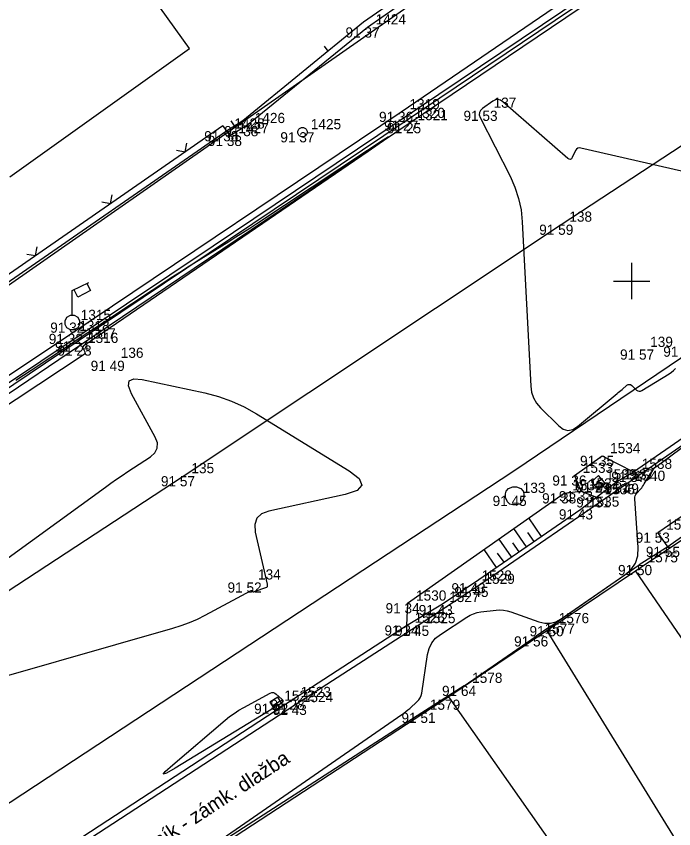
# Model space of a CAD drawing. Extents: x -711081 to -709338, y -1025122 to -1024092.
# Drawn here: x -710916.9 to -710898.84, y -1025015.05 to -1024992.72 of the extents above; entities that cross this region are included whole.
import ezdxf

# ---------------------------------------------------------------- set-up
doc = ezdxf.new("R2010")
doc.units = 0
for name, color, linetype in [('Ex_Minor Contours', 7, 'Continuous'), ('Z_body', 7, 'Continuous'), ('Z_body_cisla', 7, 'Continuous'), ('Z_body_vysky_redukovane', 7, 'Continuous'), ('Z_budova', 7, 'Continuous'), ('Z_hektometricka_sit', 7, 'Continuous'), ('Z_hrany_paty', 7, 'Continuous'), ('Z_katastr_hranice', 7, 'Continuous'), ('Z_katastr_vnitrni_kresba', 7, 'Continuous'), ('Z_komunikace', 7, 'Continuous'), ('Z_komunikace_osa', 7, 'Continuous'), ('Z_obruba', 7, 'Continuous'), ('Z_pilire', 7, 'Continuous'), ('Z_ploty', 7, 'Continuous'), ('Z_ploty_znacky', 7, 'Continuous'), ('Z_popisy', 7, 'Continuous'), ('Z_rozhranni', 7, 'Continuous'), ('Z_site_kanalizace_znaky', 7, 'Continuous'), ('Z_site_vo_znaky', 7, 'Continuous'), ('Z_site_vodovod_znaky', 7, 'Continuous'), ('Z_technicke_srafy', 7, 'Continuous'), ('Z_vstupy', 7, 'Continuous')]:
    doc.layers.add(name, color=color, linetype=linetype)

# ---------------------------------------------------------------- blocks, each defined once
blk = doc.blocks.new('POINT_DISPLAY')
blk.add_line((0, 0), (0, 0))
blk = doc.blocks.new('Z210')
blk.add_line((0, 0), (0, 0.17))
blk = doc.blocks.new('Z212')
for p, q in [((-0.17, 0.17), (0, 0)), ((0, 0), (0.17, 0.17))]:
    blk.add_line(p, q)
blk = doc.blocks.new('Z614')
for p, q in [((-0.13, 0.03), (-0.1, 0.08)), ((-0.13, -0.03), (-0.13, 0.03)), ((-0.1, 0.08), (-0.08, 0.1)), ((-0.08, 0.1), (-0.03, 0.13)), ((-0.03, 0.13), (0.03, 0.13)), ((0.03, 0.13), (0.08, 0.1)), ((0.08, 0.1), (0.1, 0.08)), ((0.1, 0.08), (0.13, 0.03)), ((0.13, 0.03), (0.13, -0.03)), ((-0.1, -0.08), (-0.13, -0.03)), ((-0.08, -0.1), (-0.1, -0.08)), ((-0.03, -0.13), (-0.08, -0.1)), ((0.03, -0.13), (-0.03, -0.13)), ((0.08, -0.1), (0.03, -0.13)), ((0.1, -0.08), (0.08, -0.1)), ((0.13, -0.03), (0.1, -0.08))]:
    blk.add_line(p, q)
blk = doc.blocks.new('Z13')
for p, q in [((0, 0.88), (0.45, 1.1)), ((0.15, 0.7), (0.05, 0.9)), ((0.4, 1.07), (0.5, 0.88)), ((0, 0.2), (0, 0.88)), ((0.5, 0.88), (0.15, 0.7)), ((-0.2, 0.05), (-0.15, 0.15)), ((-0.2, -0.05), (-0.2, 0.05)), ((-0.15, 0.15), (-0.05, 0.2)), ((-0.05, 0.2), (0.05, 0.2)), ((0.05, 0.2), (0.15, 0.15)), ((0.15, 0.15), (0.2, 0.05)), ((0.2, 0.05), (0.2, -0.05)), ((-0.15, -0.15), (-0.2, -0.05)), ((-0.05, -0.2), (-0.15, -0.15)), ((0.05, -0.2), (-0.05, -0.2)), ((0.15, -0.15), (0.05, -0.2)), ((0.2, -0.05), (0.15, -0.15))]:
    blk.add_line(p, q)
blk = doc.blocks.new('Z620')
for p, q in [((-0.17, 0.2), (-0.05, 0.25)), ((-0.05, 0.25), (0.05, 0.25)), ((0.05, 0.25), (0.17, 0.2)), ((-0.25, 0.05), (-0.23, 0.13)), ((-0.25, -0.05), (-0.25, 0.05)), ((-0.23, 0.13), (-0.17, 0.2)), ((0.17, 0.2), (0.23, 0.13)), ((0.23, 0.13), (0.25, 0.05)), ((0.25, 0.05), (0.25, -0.05)), ((-0.2, -0.17), (-0.25, -0.05)), ((-0.13, -0.23), (-0.2, -0.17)), ((0.2, -0.17), (0.13, -0.23)), ((0.25, -0.05), (0.2, -0.17)), ((-0.05, -0.25), (-0.13, -0.23)), ((0.05, -0.25), (-0.05, -0.25)), ((0.13, -0.23), (0.05, -0.25))]:
    blk.add_line(p, q)
blk = doc.blocks.new('Z46260')
for p, q in [((0.13, 0.13), (-0.13, 0.13)), ((-0.13, 0.13), (-0.13, -0.13)), ((0.13, 0), (-0.13, 0)), ((0.13, -0.13), (0.13, 0.13)), ((-0.13, -0.13), (0.13, -0.13))]:
    blk.add_line(p, q)

msp = doc.modelspace()

# ---------------------------------------------------------------- linework, layer by layer
at = {"layer": 'Ex_Minor Contours'}
for points in [[(-710896.068, -1024997.571), (-710901.392, -1024996.347), (-710901.439, -1024996.342), (-710901.479, -1024996.353), (-710901.512, -1024996.377), (-710901.539, -1024996.417), (-710901.629, -1024996.604), (-710901.654, -1024996.641), (-710901.682, -1024996.657), (-710901.715, -1024996.654), (-710901.752, -1024996.63), (-710903.534, -1024995.076), (-710903.6, -1024995.033), (-710903.668, -1024995.015), (-710903.737, -1024995.025), (-710903.807, -1024995.061), (-710904.093, -1024995.258), (-710904.15, -1024995.311), (-710904.18, -1024995.37), (-710904.182, -1024995.437), (-710904.156, -1024995.511), (-710903.336, -1024997.123), (-710903.203, -1024997.422), (-710903.103, -1024997.729), (-710903.036, -1024998.046), (-710903.003, -1024998.371), (-710902.771, -1025002.888), (-710902.747, -1025003.057), (-710902.695, -1025003.213), (-710902.613, -1025003.356), (-710902.503, -1025003.486), (-710902.002, -1025003.979), (-710901.876, -1025004.072), (-710901.747, -1025004.107), (-710901.616, -1025004.083), (-710901.482, -1025003.999), (-710900.397, -1025003.09), (-710900.364, -1025003.062), (-710900.33, -1025003.033), (-710900.296, -1025003.005), (-710900.263, -1025002.977), (-710900.128, -1025002.865), (-710900.094, -1025002.844), (-710900.061, -1025002.838), (-710900.028, -1025002.846), (-710899.996, -1025002.869), (-710899.861, -1025002.994), (-710899.827, -1025003.018), (-710899.791, -1025003.029), (-710899.755, -1025003.026), (-710899.717, -1025003.009), (-710898.969, -1025002.552), (-710898.904, -1025002.507), (-710898.845, -1025002.456), (-710898.792, -1025002.399)], [(-710920.621, -1025005.7), (-710915.035, -1025002.009), (-710915.018, -1025001.994), (-710915.01, -1025001.977), (-710915.009, -1025001.958), (-710915.017, -1025001.936), (-710915.066, -1025001.847), (-710915.074, -1025001.826), (-710915.073, -1025001.806), (-710915.065, -1025001.789), (-710915.048, -1025001.774), (-710907.239, -1024996.433), (-710906.817, -1024996.142), (-710906.678, -1024996.042), (-710906.823, -1024996.133), (-710907.251, -1024996.415), (-710910.297, -1024998.43), (-710910.486, -1024998.554), (-710910.677, -1024998.677), (-710910.868, -1024998.799), (-710911.06, -1024998.919), (-710911.831, -1024999.398), (-710912.024, -1024999.518), (-710912.215, -1024999.639), (-710912.406, -1024999.762), (-710912.595, -1024999.886), (-710914.298, -1025001.009), (-710914.393, -1025001.071), (-710914.488, -1025001.134), (-710914.584, -1025001.197), (-710914.679, -1025001.259), (-710915.061, -1025001.509), (-710915.156, -1025001.571), (-710915.251, -1025001.634), (-710915.346, -1025001.697), (-710915.441, -1025001.76), (-710916.495, -1025002.457), (-710916.703, -1025002.594), (-710916.91, -1025002.731)], [(-710919.801, -1025009.546), (-710914.45, -1025005.662), (-710914.299, -1025005.553), (-710914.146, -1025005.446), (-710913.992, -1025005.341), (-710913.838, -1025005.237), (-710913.216, -1025004.826), (-710913.091, -1025004.716), (-710913.027, -1025004.59), (-710913.024, -1025004.449), (-710913.082, -1025004.293), (-710913.733, -1025003.095), (-710913.818, -1025002.88), (-710913.798, -1025002.744), (-710913.673, -1025002.686), (-710913.443, -1025002.707), (-710911.723, -1025003.075), (-710911.349, -1025003.172), (-710910.986, -1025003.3), (-710910.636, -1025003.458), (-710910.298, -1025003.647), (-710907.754, -1025005.214), (-710907.481, -1025005.427), (-710907.408, -1025005.606), (-710907.536, -1025005.751), (-710907.865, -1025005.862), (-710909.961, -1025006.318), (-710910.165, -1025006.393), (-710910.295, -1025006.516), (-710910.351, -1025006.686), (-710910.334, -1025006.902), (-710910.012, -1025008.327), (-710910.01, -1025008.335), (-710910.009, -1025008.343), (-710910.008, -1025008.352), (-710910.009, -1025008.36), (-710910.01, -1025008.394), (-710910.012, -1025008.402), (-710910.015, -1025008.408), (-710910.02, -1025008.413), (-710910.027, -1025008.417), (-710910.376, -1025008.543), (-710910.383, -1025008.544), (-710910.391, -1025008.544), (-710910.398, -1025008.541), (-710910.404, -1025008.537), (-710910.429, -1025008.514), (-710910.435, -1025008.509), (-710910.442, -1025008.507), (-710910.449, -1025008.507), (-710910.456, -1025008.51), (-710911.718, -1025009.187), (-710911.933, -1025009.295), (-710912.153, -1025009.392), (-710912.378, -1025009.476), (-710912.608, -1025009.548), (-710918.944, -1025011.362)], [(-710912.431, -1025016.148), (-710906.311, -1025011.912), (-710906.254, -1025011.871), (-710906.199, -1025011.829), (-710906.145, -1025011.785), (-710906.093, -1025011.74), (-710905.885, -1025011.554), (-710905.839, -1025011.505), (-710905.802, -1025011.45), (-710905.777, -1025011.39), (-710905.761, -1025011.324), (-710905.603, -1025010.259), (-710905.561, -1025010.092), (-710905.489, -1025009.944), (-710905.385, -1025009.816), (-710905.25, -1025009.707), (-710904.525, -1025009.231), (-710904.435, -1025009.179), (-710904.341, -1025009.139), (-710904.243, -1025009.109), (-710904.141, -1025009.091), (-710903.723, -1025009.043), (-710903.62, -1025009.036), (-710903.517, -1025009.042), (-710903.416, -1025009.059), (-710903.317, -1025009.089), (-710902.544, -1025009.365), (-710902.384, -1025009.403), (-710902.23, -1025009.402), (-710902.081, -1025009.363), (-710901.937, -1025009.285), (-710900.182, -1025008.071), (-710900.013, -1025007.923), (-710899.896, -1025007.749), (-710899.832, -1025007.549), (-710899.822, -1025007.324), (-710899.912, -1025005.982), (-710899.911, -1025005.941), (-710899.902, -1025005.903), (-710899.885, -1025005.867), (-710899.861, -1025005.835), (-710899.748, -1025005.709), (-710899.721, -1025005.677), (-710899.696, -1025005.643), (-710899.672, -1025005.609), (-710899.65, -1025005.573), (-710899.484, -1025005.285), (-710899.447, -1025005.227), (-710899.404, -1025005.174), (-710899.357, -1025005.126), (-710899.303, -1025005.083), (-710897.795, -1025003.971)]]:
    msp.add_lwpolyline(points, dxfattribs=at)
msp.add_lwpolyline([(-710912.772, -1025013.521), (-710912.863, -1025013.551), (-710912.806, -1025013.474), (-710912.601, -1025013.29), (-710911.163, -1025012.066), (-710911.043, -1025011.968), (-710910.918, -1025011.878), (-710910.788, -1025011.794), (-710910.654, -1025011.717), (-710909.923, -1025011.325), (-710909.879, -1025011.308), (-710909.837, -1025011.306), (-710909.797, -1025011.319), (-710909.758, -1025011.347), (-710909.61, -1025011.486), (-710909.582, -1025011.519), (-710909.575, -1025011.551), (-710909.589, -1025011.581), (-710909.622, -1025011.608), (-710912.533, -1025013.384)], close=True, dxfattribs=at)
at = {"layer": 'Z_budova'}
for p, q in [((-710897.68, -1025006.36), (-710899, -1025007.3)), ((-710899, -1025007.3), (-710899.79, -1025007.8)), ((-710902.22, -1025009.48), (-710902.62, -1025009.76)), ((-710904.6, -1025011.12), (-710905.76, -1025011.86)), ((-710905.76, -1025011.86), (-710912.65, -1025016.3))]:
    msp.add_line(p, q, dxfattribs=at)
at = {"layer": 'Z_hektometricka_sit'}
for p, q in [((-710900, -1024999.5), (-710900, -1025000.5)), ((-710900.5, -1025000), (-710899.5, -1025000))]:
    msp.add_line(p, q, dxfattribs=at)
at = {"layer": 'Z_hrany_paty'}
for p, q in [((-710901.57, -1025005.34), (-710900.81, -1025004.8)), ((-710900.81, -1025004.8), (-710899.95, -1025005.24)), ((-710901.57, -1025005.34), (-710901.39, -1025005.77)), ((-710906.15, -1025008.85), (-710901.85, -1025005.83)), ((-710901.85, -1025005.83), (-710901.39, -1025005.77)), ((-710901.39, -1025005.77), (-710900.96, -1025005.94)), ((-710906.15, -1025008.85), (-710906.18, -1025009.46))]:
    msp.add_line(p, q, dxfattribs=at)
at = {"layer": 'Z_katastr_hranice'}
for p, q in [((-710912.14, -1024993.61), (-710920.13, -1024982.44)), ((-710902.22, -1024989.72), (-710924.85, -1025005.52)), ((-710899.64, -1024991.07), (-710911.49, -1024999.04)), ((-710917.08, -1024997.14), (-710912.14, -1024993.61)), ((-710903.23, -1025005.21), (-710890.97, -1024996.92)), ((-710911.49, -1024999.04), (-710935.4, -1025015.03)), ((-710887.15, -1024999.45), (-710899.89, -1025007.97)), ((-710931.09, -1025023.55), (-710903.23, -1025005.21)), ((-710899.89, -1025007.97), (-710902.33, -1025009.61)), ((-710899.89, -1025007.97), (-710894.9, -1025015.28)), ((-710902.33, -1025009.61), (-710905.02, -1025011.42)), ((-710905.02, -1025011.42), (-710916.8, -1025019.12)), ((-710900.29, -1025018.16), (-710905.02, -1025011.42))]:
    msp.add_line(p, q, dxfattribs=at)
at = {"layer": 'Z_katastr_vnitrni_kresba'}
msp.add_line((-710902.33, -1025009.61), (-710897.59, -1025017.29), dxfattribs=at)
at = {"layer": 'Z_komunikace'}
for p, q in [((-710906.19, -1024995.59), (-710901.08, -1024992.14)), ((-710915.23, -1025001.66), (-710906.19, -1024995.59)), ((-710899.95, -1025005.24), (-710888.72, -1024997.46)), ((-710926.84, -1025009.47), (-710915.23, -1025001.66)), ((-710900.43, -1025005.53), (-710899.95, -1025005.24)), ((-710900.96, -1025005.94), (-710900.43, -1025005.53)), ((-710901.39, -1025006.27), (-710900.96, -1025005.94)), ((-710904.34, -1025008.3), (-710901.39, -1025006.27)), ((-710905.24, -1025008.9), (-710904.34, -1025008.3)), ((-710906.18, -1025009.46), (-710905.24, -1025008.9)), ((-710909.31, -1025011.5), (-710906.18, -1025009.46)), ((-710918.97, -1025017.8), (-710909.31, -1025011.5))]:
    msp.add_line(p, q, dxfattribs=at)
at = {"layer": 'Z_komunikace_osa'}
for p, q in [((-710901.93, -1024998.45), (-710887.53, -1024988.98)), ((-710912.32, -1025005.36), (-710901.93, -1024998.45)), ((-710919.86, -1025010.3), (-710912.32, -1025005.36))]:
    msp.add_line(p, q, dxfattribs=at)
at = {"layer": 'Z_obruba'}
for p, q in [((-710906.33, -1024995.35), (-710901.28, -1024991.9)), ((-710915.4, -1025001.45), (-710906.33, -1024995.35)), ((-710900.13, -1025005.56), (-710888.63, -1024997.61)), ((-710926.99, -1025009.16), (-710915.4, -1025001.45)), ((-710904.26, -1025008.4), (-710900.13, -1025005.56)), ((-710905.89, -1025009.47), (-710904.26, -1025008.4)), ((-710909.25, -1025011.64), (-710905.89, -1025009.47)), ((-710918.97, -1025017.98), (-710909.25, -1025011.64))]:
    msp.add_line(p, q, dxfattribs=at)
at = {"layer": 'Z_pilire'}
for p, q in [((-710899.28, -1025006.91), (-710897.94, -1025005.99)), ((-710899, -1025007.3), (-710899.28, -1025006.91))]:
    msp.add_line(p, q, dxfattribs=at)
at = {"layer": 'Z_ploty'}
for p, q in [((-710902.49, -1024989.49), (-710907.36, -1024992.89)), ((-710902.63, -1024989.8), (-710907.25, -1024993.03)), ((-710907.36, -1024992.89), (-710910.68, -1024995.6)), ((-710907.25, -1024993.03), (-710910.58, -1024995.74)), ((-710910.68, -1024995.6), (-710911.13, -1024995.88)), ((-710911.23, -1024995.74), (-710920.46, -1025002.14)), ((-710911.13, -1024995.88), (-710920.36, -1025002.28)), ((-710911.23, -1024995.74), (-710911.13, -1024995.88)), ((-710911.13, -1024995.88), (-710911.03, -1024996.01)), ((-710910.58, -1024995.74), (-710911.03, -1024996.01))]:
    msp.add_line(p, q, dxfattribs=at)
at = {"layer": 'Z_rozhranni'}
for p, q in [((-710906.11, -1024995.66), (-710901.02, -1024992.22)), ((-710915.16, -1025001.77), (-710906.11, -1024995.66)), ((-710926.79, -1025009.58), (-710915.16, -1025001.77))]:
    msp.add_line(p, q, dxfattribs=at)
at = {"layer": 'Z_technicke_srafy'}
for p, q in [((-710902.47, -1025007.02), (-710902.82, -1025006.51)), ((-710902.89, -1025007.3), (-710903.23, -1025006.8)), ((-710902.68, -1025007.16), (-710902.85, -1025006.91)), ((-710903.3, -1025007.58), (-710903.64, -1025007.09)), ((-710903.09, -1025007.44), (-710903.26, -1025007.19)), ((-710903.71, -1025007.87), (-710904.05, -1025007.38)), ((-710903.5, -1025007.72), (-710903.68, -1025007.48))]:
    msp.add_line(p, q, dxfattribs=at)
at = {"layer": 'Z_vstupy'}
for p, q in [((-710902.22, -1025009.48), (-710899.79, -1025007.8)), ((-710904.6, -1025011.12), (-710902.62, -1025009.76))]:
    msp.add_line(p, q, dxfattribs=at)

# ---------------------------------------------------------------- block references
at = {"layer": 'Z_body'}
for p in [(-710907.25, -1024993.03), (-710906.33, -1024995.35), (-710904.01, -1024995.32), (-710906.19, -1024995.59), (-710906.11, -1024995.66), (-710911.13, -1024995.88), (-710910.58, -1024995.74), (-710909.04, -1024995.91), (-710911.03, -1024996.01), (-710901.93, -1024998.45), (-710915.36, -1025001.14), (-710915.4, -1025001.45), (-710915.23, -1025001.66), (-710915.16, -1025001.77), (-710899.71, -1025001.88), (-710914.25, -1025002.19), (-710900.81, -1025004.8), (-710899.95, -1025005.24), (-710912.32, -1025005.36), (-710901.57, -1025005.34), (-710900.92, -1025005.53), (-710900.43, -1025005.53), (-710900.13, -1025005.56), (-710903.21, -1025005.9), (-710901.85, -1025005.83), (-710901.39, -1025005.77), (-710900.96, -1025005.94), (-710901.39, -1025006.27), (-710899.28, -1025006.91), (-710899, -1025007.3), (-710899.79, -1025007.8), (-710910.49, -1025008.28), (-710904.34, -1025008.3), (-710904.26, -1025008.4), (-710906.15, -1025008.85), (-710905.24, -1025008.9), (-710906.18, -1025009.46), (-710905.89, -1025009.47), (-710902.22, -1025009.48), (-710902.62, -1025009.76), (-710904.6, -1025011.12), (-710909.31, -1025011.5), (-710909.76, -1025011.61), (-710909.25, -1025011.64), (-710905.76, -1025011.86)]:
    msp.add_blockref('POINT_DISPLAY', p, dxfattribs=at)
at = {"layer": 'Z_ploty_znacky'}
for name, p, rotation in [('Z210', (-710908.33, -1024993.68), 39.1), ('Z210', (-710910.91, -1024995.74), 32.2), ('Z212', (-710912.26, -1024996.45), 34.699999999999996), ('Z212', (-710914.31, -1024997.87), 34.699999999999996), ('Z212', (-710916.37, -1024999.3), 34.699999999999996)]:
    msp.add_blockref(name, p, dxfattribs=dict(at, rotation=rotation))
at = {"layer": 'Z_site_kanalizace_znaky'}
for p, rotation in [((-710900.92, -1025005.53), 41.39999999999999), ((-710909.76, -1025011.61), 32.4)]:
    msp.add_blockref('Z46260', p, dxfattribs=dict(at, rotation=rotation))
msp.add_blockref('Z620', (-710903.21, -1025005.9), dxfattribs=at)
at = {"layer": 'Z_site_vo_znaky'}
msp.add_blockref('Z13', (-710915.36, -1025001.14), dxfattribs=at)
at = {"layer": 'Z_site_vodovod_znaky'}
msp.add_blockref('Z614', (-710909.04, -1024995.91), dxfattribs=at)

# ---------------------------------------------------------------- texts
at = {"layer": 'Z_body_cisla'}
for s, p in [('1424', (-710907.03, -1024992.95)), ('1319', (-710906.1, -1024995.28)), ('137', (-710903.79, -1024995.24)), ('1320', (-710905.96, -1024995.52)), ('1426', (-710910.35, -1024995.66)), ('1321', (-710905.88, -1024995.58)), ('1428', (-710910.91, -1024995.81)), ('1427', (-710910.8, -1024995.94)), ('1425', (-710908.81, -1024995.83)), ('138', (-710901.71, -1024998.37)), ('1315', (-710915.13, -1025001.07)), ('1318', (-710915.17, -1025001.37)), ('1317', (-710915, -1025001.58)), ('1316', (-710914.93, -1025001.7)), ('139', (-710899.49, -1025001.81)), ('136', (-710914.03, -1025002.11)), ('1534', (-710900.59, -1025004.73)), ('135', (-710912.09, -1025005.28)), ('1533', (-710901.34, -1025005.27)), ('1538', (-710899.72, -1025005.16)), ('1539', (-710900.7, -1025005.45)), ('1537', (-710900.21, -1025005.45)), ('1540', (-710899.91, -1025005.49)), ('1531', (-710901.63, -1025005.75)), ('1532', (-710901.17, -1025005.7)), ('133', (-710902.99, -1025005.82)), ('1536', (-710900.74, -1025005.86)), ('1535', (-710901.17, -1025006.2)), ('1573', (-710899.05, -1025006.83)), ('1575', (-710899.56, -1025007.73)), ('134', (-710910.26, -1025008.2)), ('1528', (-710904.12, -1025008.23)), ('1529', (-710904.04, -1025008.32)), ('1530', (-710905.92, -1025008.78)), ('1527', (-710905.01, -1025008.82)), ('1526', (-710905.96, -1025009.39)), ('1525', (-710905.67, -1025009.4)), ('1576', (-710902, -1025009.4)), ('1577', (-710902.39, -1025009.69)), ('1578', (-710904.38, -1025011.04)), ('1522', (-710909.54, -1025011.53)), ('1523', (-710909.09, -1025011.43)), ('1524', (-710909.03, -1025011.57)), ('1579', (-710905.54, -1025011.78))]:
    msp.add_text(s, height=0.28, dxfattribs=at).set_placement(p)
at = {"layer": 'Z_body_vysky_redukovane'}
for s, p in [('91 37', (-710907.857, -1024993.31)), ('91 36', (-710906.937, -1024995.63)), ('91 53', (-710904.617, -1024995.6)), ('91 27', (-710906.797, -1024995.87)), ('91 25', (-710906.717, -1024995.94)), ('91 38', (-710911.737, -1024996.16)), ('91 38', (-710911.187, -1024996.02)), ('91 37', (-710909.647, -1024996.19)), ('91 38', (-710911.637, -1024996.29)), ('91 59', (-710902.537, -1024998.73)), ('91 32', (-710915.967, -1025001.42)), ('91 32', (-710916.007, -1025001.73)), ('91 24', (-710915.837, -1025001.94)), ('91 23', (-710915.767, -1025002.05)), ('91 57', (-710900.317, -1025002.16)), ('91 51', (-710899.13, -1025002.08)), ('91 49', (-710914.857, -1025002.47)), ('91 35', (-710901.417, -1025005.08)), ('91 37', (-710900.557, -1025005.52)), ('91 57', (-710912.927, -1025005.64)), ('91 36', (-710902.177, -1025005.62)), ('91 29', (-710901.527, -1025005.81)), ('91 31', (-710900.99, -1025005.81)), ('91 49', (-710900.737, -1025005.84)), ('91 45', (-710903.817, -1025006.18)), ('91 38', (-710902.457, -1025006.11)), ('91 33', (-710901.997, -1025006.05)), ('91 31', (-710901.52, -1025006.22)), ('91 43', (-710901.997, -1025006.55)), ('91 53', (-710899.887, -1025007.19)), ('91 55', (-710899.607, -1025007.58)), ('91 50', (-710900.373, -1025008.08)), ('91 52', (-710911.097, -1025008.56)), ('91 43', (-710904.947, -1025008.58)), ('91 45', (-710904.867, -1025008.68)), ('91 34', (-710906.757, -1025009.13)), ('91 43', (-710905.847, -1025009.18)), ('91 34', (-710906.787, -1025009.74)), ('91 45', (-710906.497, -1025009.75)), ('91 50', (-710902.803, -1025009.76)), ('91 56', (-710903.227, -1025010.04)), ('91 64', (-710905.207, -1025011.4)), ('91 28', (-710909.917, -1025011.78)), ('91 22', (-710910.367, -1025011.89)), ('91 43', (-710909.857, -1025011.92)), ('91 51', (-710906.32, -1025012.14))]:
    msp.add_text(s, height=0.28, dxfattribs=at).set_placement(p)
at = {"layer": 'Z_popisy'}
msp.add_text('Chodník - zámk. dlažba', height=0.4, rotation=33.3, dxfattribs=at).set_placement((-710914.05, -1025016.29))

doc.saveas('drawing.dxf')
